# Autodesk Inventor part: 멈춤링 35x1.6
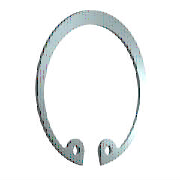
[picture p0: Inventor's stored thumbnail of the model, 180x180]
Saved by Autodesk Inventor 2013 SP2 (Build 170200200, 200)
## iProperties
IsCustomPart: 1
Created: 2012-02
Part Number: 멈춤링 35x1.6
Material: 강철, 연강
Description: 리테이닝 링(C형)
Document SubType Name: Modeling
Standard: KS B 1336
Designer: mduedu
Standards Organization: KS
Language: ko-KR
Size Designation: 35x1.6
Categories: <MemberInstance><Categories><Category DisplayName="샤프트 부품" InternalName="7f7aeb1f-a693-4053-b835-cee3144e0d98" Mnemonic="SHFT"><Category DisplayName="써클립" Inter
Density: 1 g/cm^3
Author: mduedu
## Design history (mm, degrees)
sketch "스케치1"
  geometry: L1 (0, 15.113)-(0, -73.177) reference; L2 (-45.5, 0)-(45.5, 0) reference; L3 (-4.964, 1)-(1.502, 1); L4 (0, -2.5)-(-5.307, -2.5); L5 (0, -17.5)-(-8.583, -33.888); L6 (-8.583, -33.888)-(-21.772, -26.981); L7 (-7.377, -31.585)-(-17.631, -26.214); L8 (-5.162, -32.745)-(-6.29, -34.898); L9 (5.162, -32.745)-(6.29, -34.898); C1 r 1.25 at (-7.377, -31.585); C2 r 1.25 at (7.377, -31.585); A1 r 15.875 centre (0, -18.375) between (11.82, -28.972) and (-11.82, -28.972); A2 r 18.5 centre (0, -17.5) between (6.29, -34.898) and (-6.29, -34.898); A3 r 2.5 centre (-7.377, -31.585) between (-5.162, -32.745) and (-8.668, -29.444); A4 r 2.5 centre (-9.959, -27.303) between (-11.82, -28.972) and (-8.668, -29.444); A5 r 2.5 centre (9.959, -27.303) between (8.668, -29.444) and (11.82, -28.972); A6 r 2.5 centre (7.377, -31.585) between (8.668, -29.444) and (5.162, -32.745); 3 further points
  constraints: 15 point on circle, 14 end point, 9 symmetric about line, 8 centre point, 6 tangent, 4 coincident, 4 point on line, 3 perpendicular, 1 parallel, 4 other
  dimensions: "d8" = 0.875 distance of A1.centre L5.start (= 0.25 x SRB1); "d38" = 3.5 distance between parallel lines of L4 L3 (= SRB1); "d39" = 17.5 distance from line of L5.start L2 (= 0.5 x WD); "d43" = 18.5 radius of A2 (= 0.5 x ND); "d45" = 2.6 distance between parallel lines of L7 L6 (= 0.5 x SRB2); "d46" = 2.5 radius of A4 (= SD5); "d47" = 6.29 distance from line of L1 L8.end (= 0.17 x ND); "d48" = 2.5 diameter of C1 (= SD5); "d49" = 2.5 radius of A3 (= SD5)
extrude "본체" new body sketch "스케치1" distance "d2" = 1.6 (= SD); taper "d3" = 0 deg
workaxis "Work Axis1"
workaxis "Work Axis2"
workplane "Work Plane1"
body "Solid1"
other parameters: "WD" = 35 [user parameter; used in 3 equation terms], "SD" = 1.6 [user parameter; used in 1 equation term], "SRB1" = 3.5 [user parameter; used in 2 equation terms], "ND" = 37 [user parameter; used in 2 equation terms], "SRB2" = 5.2 [user parameter; used in 1 equation term], "SD5" = 2.5 [user parameter; used in 3 equation terms], "d50" = 0, "d51" = 0, "d52" = 0, "d53" = 0, "WDMIN" = 34 [user parameter], "SD6" = 37.8 [user parameter], "WDMAX" = 35 (= WD) [user parameter], "NND" = 35 (= WD) [user parameter]
